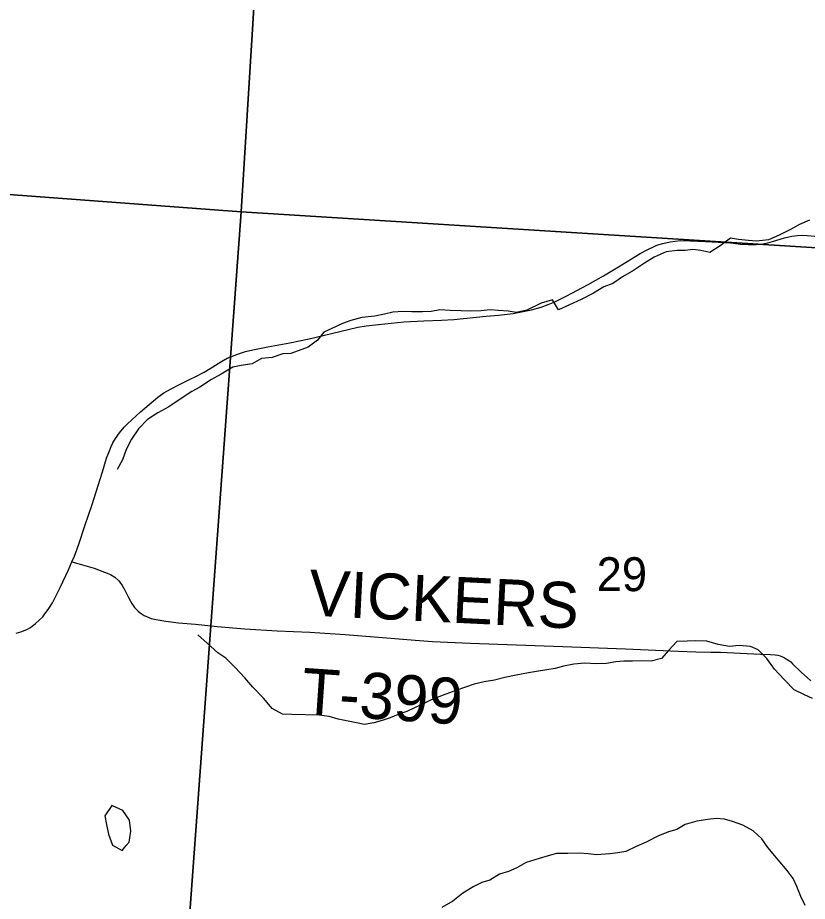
# Model space of a CAD drawing. Extents: x 0 to 34, y 0 to 22.
# Drawn here: x 4.184 to 5.158, y 17.019 to 18.11 of the extents above; entities that cross this region are included whole.
import ezdxf

# ---------------------------------------------------------------- set-up
doc = ezdxf.new("R2010")
doc.units = 0
for name, color, linetype in [('GM_X_Corporation', 7, 'Continuous'), ('GM_X_County_Road', 7, 'Continuous'), ('GM_X_Minor_Lake', 7, 'Continuous'), ('GM_X_Minor_River', 7, 'Continuous'), ('GM_X_Section_Text', 7, 'Continuous'), ('GM_X_Township_Road', 7, 'Continuous'), ('GM_X_Township_Road_Text', 7, 'Continuous')]:
    doc.layers.add(name, color=color, linetype=linetype)

msp = doc.modelspace()

# ---------------------------------------------------------------- linework, layer by layer
at = {"layer": 'GM_X_Corporation'}
for points in [[(3.5166, 18.9866), (4.5247, 18.9179), (4.4596, 17.8697), (3.4457, 17.9455)], [(4.5309, 18.9179), (5.5263, 18.8526), (5.4592, 17.8072), (4.4596, 17.8697), (4.5247, 18.9179)], [(3.4457, 17.9455), (4.4596, 17.8697), (4.3853, 16.8539), (3.3779, 16.9127)], [(4.4596, 17.8697), (5.4592, 17.8072), (5.3901, 16.7843), (4.3853, 16.8539)]]:
    msp.add_lwpolyline(points, close=True, dxfattribs=at)
at = {"layer": 'GM_X_County_Road'}
msp.add_lwpolyline([(4.1821, 17.3498), (4.1877, 17.3514), (4.1934, 17.3536), (4.1961, 17.3549), (4.1988, 17.3563), (4.2013, 17.358), (4.2061, 17.3618), (4.2106, 17.3659), (4.2149, 17.3702), (4.2168, 17.3725), (4.2225, 17.3803), (4.2269, 17.3874), (4.2365, 17.4062), (4.2468, 17.428), (4.2509, 17.4377), (4.254, 17.4449), (4.2595, 17.4596), (4.2669, 17.4824), (4.276, 17.5087), (4.2858, 17.5399), (4.2885, 17.549), (4.2937, 17.5659), (4.2965, 17.5729), (4.2992, 17.5802), (4.3014, 17.5848), (4.3045, 17.5901), (4.3096, 17.5973), (4.3153, 17.604), (4.3195, 17.6084), (4.3355, 17.6229), (4.3569, 17.641), (4.3645, 17.6464), (4.3725, 17.6512), (4.3835, 17.6569), (4.3975, 17.6636), (4.4031, 17.6661), (4.4139, 17.6718), (4.4217, 17.6765), (4.4345, 17.6847), (4.4425, 17.6893), (4.4566, 17.6946), (4.4653, 17.6973), (4.4743, 17.6995), (4.4925, 17.7032), (4.52, 17.7082), (4.5438, 17.7133), (4.5711, 17.7196), (4.6039, 17.7275), (4.6142, 17.7292), (4.6294, 17.731), (4.6605, 17.734), (4.6853, 17.7355), (4.707, 17.736), (4.7221, 17.737), (4.7622, 17.7411), (4.7772, 17.7424), (4.7955, 17.7444), (4.818, 17.7491), (4.83, 17.7523), (4.8386, 17.7554), (4.8469, 17.7588), (4.8607, 17.7656), (4.888, 17.7803), (4.907, 17.7909), (4.9256, 17.802), (4.952, 17.8183), (4.96, 17.8227), (4.9711, 17.8278), (4.974, 17.829), (4.98, 17.8308), (4.9891, 17.8329), (4.9953, 17.8338), (5.0016, 17.8343), (5.014, 17.8342), (5.0327, 17.8334), (5.0636, 17.8315), (5.0699, 17.8308), (5.0761, 17.83), (5.0854, 17.8296), (5.0952, 17.8295), (5.1007, 17.8298), (5.1037, 17.8302), (5.1097, 17.8315), (5.1156, 17.8331), (5.1304, 17.8377), (5.1395, 17.8398), (5.1457, 17.8407), (5.152, 17.841), (5.1583, 17.8407), (5.1676, 17.8397)], dxfattribs=at)
at = {"layer": 'GM_X_Minor_Lake'}
for p, q in [((4.3003, 17.1371), (4.2916, 17.1246)), ((4.3136, 17.1311), (4.3003, 17.1371)), ((4.2916, 17.1246), (4.2936, 17.1136)), ((4.3219, 17.1191), (4.3136, 17.1311)), ((4.2936, 17.1136), (4.2959, 17.1019)), ((4.3235, 17.1054), (4.3219, 17.1191)), ((4.2959, 17.1019), (4.3008, 17.0883)), ((4.3216, 17.0921), (4.3235, 17.1054)), ((4.318, 17.0876), (4.3216, 17.0921)), ((4.3008, 17.0883), (4.313, 17.0815)), ((4.313, 17.0815), (4.318, 17.0876))]:
    msp.add_line(p, q, dxfattribs=at)
at = {"layer": 'GM_X_Minor_River'}
for p, q in [((5.1487, 17.8544), (5.1378, 17.8479)), ((5.1612, 17.8595), (5.1487, 17.8544)), ((5.1378, 17.8479), (5.1235, 17.8409)), ((5.0637, 17.8374), (5.051, 17.8278)), ((5.0736, 17.8359), (5.0637, 17.8374)), ((5.0857, 17.8345), (5.0736, 17.8359)), ((5.0956, 17.8338), (5.0857, 17.8345)), ((5.1103, 17.8355), (5.0956, 17.8338)), ((5.1235, 17.8409), (5.1103, 17.8355)), ((4.9977, 17.822), (4.9844, 17.8207)), ((5.0075, 17.8221), (4.9977, 17.822)), ((5.0173, 17.8233), (5.0075, 17.8221)), ((5.0272, 17.8222), (5.0173, 17.8233)), ((5.0382, 17.8197), (5.0272, 17.8222)), ((5.051, 17.8278), (5.0382, 17.8197)), ((4.9694, 17.8141), (4.9573, 17.8064)), ((4.9844, 17.8207), (4.9694, 17.8141)), ((4.9573, 17.8064), (4.9438, 17.7976)), ((4.9302, 17.7895), (4.9186, 17.7815)), ((4.9438, 17.7976), (4.9302, 17.7895)), ((4.9072, 17.7772), (4.8944, 17.7695)), ((4.9186, 17.7815), (4.9072, 17.7772)), ((4.8944, 17.7695), (4.8794, 17.7618)), ((4.8299, 17.7572), (4.8121, 17.7487)), ((4.8438, 17.7611), (4.8299, 17.7572)), ((4.8515, 17.749), (4.8438, 17.7611)), ((4.8794, 17.7618), (4.8651, 17.7552)), ((4.6468, 17.746), (4.6366, 17.7437)), ((4.6597, 17.7469), (4.6468, 17.746)), ((4.6703, 17.7466), (4.6597, 17.7469)), ((4.6835, 17.7464), (4.6703, 17.7466)), ((4.6941, 17.7468), (4.6835, 17.7464)), ((4.7051, 17.7488), (4.6941, 17.7468)), ((4.7176, 17.7482), (4.7051, 17.7488)), ((4.7312, 17.7475), (4.7176, 17.7482)), ((4.7429, 17.7473), (4.7312, 17.7475)), ((4.7558, 17.7478), (4.7429, 17.7473)), ((4.7671, 17.749), (4.7558, 17.7478)), ((4.7773, 17.748), (4.7671, 17.749)), ((4.7891, 17.7473), (4.7773, 17.748)), ((4.7997, 17.7455), (4.7891, 17.7473)), ((4.8121, 17.7487), (4.7997, 17.7455)), ((4.8651, 17.7552), (4.8515, 17.749)), ((4.5951, 17.7357), (4.5849, 17.7322)), ((4.6087, 17.7396), (4.5951, 17.7357)), ((4.6245, 17.7409), (4.6087, 17.7396)), ((4.6366, 17.7437), (4.6245, 17.7409)), ((4.5717, 17.726), (4.5619, 17.7214)), ((4.5849, 17.7322), (4.5717, 17.726)), ((4.5619, 17.7214), (4.5541, 17.7115)), ((4.5424, 17.703), (4.5212, 17.6952)), ((4.5541, 17.7115), (4.5424, 17.703)), ((4.4982, 17.6902), (4.4849, 17.689)), ((4.511, 17.6948), (4.4982, 17.6902)), ((4.5212, 17.6952), (4.511, 17.6948)), ((4.4596, 17.6802), (4.4494, 17.6783)), ((4.4732, 17.6822), (4.4596, 17.6802)), ((4.4849, 17.689), (4.4732, 17.6822)), ((4.435, 17.6695), (4.423, 17.663)), ((4.4494, 17.6783), (4.435, 17.6695)), ((4.423, 17.663), (4.4086, 17.6534)), ((4.3988, 17.6481), (4.3833, 17.6378)), ((4.4086, 17.6534), (4.3988, 17.6481)), ((4.3833, 17.6378), (4.3705, 17.6294)), ((4.3705, 17.6294), (4.3569, 17.6218)), ((4.3569, 17.6218), (4.344, 17.6134)), ((4.344, 17.6134), (4.3331, 17.6019)), ((4.3331, 17.6019), (4.3244, 17.5894)), ((4.3244, 17.5894), (4.318, 17.5765)), ((4.318, 17.5765), (4.3132, 17.5636)), ((4.3132, 17.5636), (4.3068, 17.5518)), ((4.4177, 17.3374), (4.4063, 17.3476)), ((4.431, 17.3257), (4.4177, 17.3374)), ((4.9973, 17.3396), (4.9876, 17.3289)), ((5.0102, 17.3401), (4.9973, 17.3396)), ((5.02, 17.3402), (5.0102, 17.3401)), ((5.0344, 17.3399), (5.02, 17.3402)), ((5.0484, 17.3359), (5.0344, 17.3399)), ((5.0624, 17.3333), (5.0484, 17.3359)), ((5.0745, 17.3346), (5.0624, 17.3333)), ((5.0882, 17.3336), (5.0745, 17.3346)), ((5.0977, 17.3291), (5.0882, 17.3336)), ((4.4408, 17.3189), (4.431, 17.3257)), ((4.9876, 17.3289), (4.9786, 17.3186)), ((5.1084, 17.3186), (5.0977, 17.3291)), ((4.4522, 17.3076), (4.4408, 17.3189)), ((4.8576, 17.3091), (4.8474, 17.3064)), ((4.8704, 17.3115), (4.8576, 17.3091)), ((4.884, 17.3128), (4.8704, 17.3115)), ((4.8977, 17.3121), (4.884, 17.3128)), ((4.9105, 17.3126), (4.8977, 17.3121)), ((4.9222, 17.3143), (4.9105, 17.3126)), ((4.9321, 17.3151), (4.9222, 17.3143)), ((4.9427, 17.3152), (4.9321, 17.3151)), ((4.9548, 17.3157), (4.9427, 17.3152)), ((4.9657, 17.3154), (4.9548, 17.3157)), ((4.9786, 17.3186), (4.9657, 17.3154)), ((5.1179, 17.3054), (5.1084, 17.3186)), ((4.4644, 17.2948), (4.4522, 17.3076)), ((4.799, 17.298), (4.7851, 17.2952)), ((4.8142, 17.3008), (4.799, 17.298)), ((4.824, 17.3024), (4.8142, 17.3008)), ((4.8368, 17.3048), (4.824, 17.3024)), ((4.8474, 17.3064), (4.8368, 17.3048)), ((5.1298, 17.2927), (5.1179, 17.3054)), ((4.4743, 17.2831), (4.4644, 17.2948)), ((4.7473, 17.2869), (4.7367, 17.2834)), ((4.7598, 17.2897), (4.7473, 17.2869)), ((4.7722, 17.2917), (4.7598, 17.2897)), ((4.7851, 17.2952), (4.7722, 17.2917)), ((5.142, 17.2799), (5.1298, 17.2927)), ((4.4875, 17.2695), (4.4743, 17.2831)), ((4.7247, 17.2791), (4.7092, 17.2733)), ((4.7367, 17.2834), (4.7247, 17.2791)), ((5.1549, 17.2739), (5.142, 17.2799)), ((4.4978, 17.257), (4.4875, 17.2695)), ((4.6941, 17.2675), (4.6843, 17.2628)), ((4.7092, 17.2733), (4.6941, 17.2675)), ((5.1648, 17.2691), (5.1549, 17.2739)), ((4.5107, 17.2499), (4.4978, 17.257)), ((4.6738, 17.2578), (4.664, 17.2532)), ((4.6843, 17.2628), (4.6738, 17.2578)), ((4.5219, 17.2495), (4.5107, 17.2499)), ((4.5562, 17.2488), (4.5219, 17.2495)), ((4.5683, 17.247), (4.5562, 17.2488)), ((4.5793, 17.2437), (4.5683, 17.247)), ((4.602, 17.2393), (4.5793, 17.2437)), ((4.6436, 17.2454), (4.6338, 17.2419)), ((4.6534, 17.2493), (4.6436, 17.2454)), ((4.664, 17.2532), (4.6534, 17.2493)), ((4.6119, 17.2372), (4.602, 17.2393)), ((4.6236, 17.2392), (4.6119, 17.2372)), ((4.6338, 17.2419), (4.6236, 17.2392)), ((5.0076, 17.1138), (4.9974, 17.1077)), ((5.0219, 17.1177), (5.0076, 17.1138)), ((5.0356, 17.1198), (5.0219, 17.1177)), ((5.0461, 17.121), (5.0356, 17.1198)), ((5.0564, 17.1203), (5.0461, 17.121)), ((5.0662, 17.1174), (5.0564, 17.1203)), ((5.0787, 17.1129), (5.0662, 17.1174)), ((5.0917, 17.1059), (5.0787, 17.1129)), ((4.9869, 17.1045), (4.9741, 17.0995)), ((4.9974, 17.1077), (4.9869, 17.1045)), ((5.1023, 17.0961), (5.0917, 17.1059)), ((4.9597, 17.0918), (4.9462, 17.086)), ((4.9741, 17.0995), (4.9597, 17.0918)), ((5.1096, 17.0852), (5.1023, 17.0961)), ((4.9345, 17.0802), (4.9247, 17.0786)), ((4.9462, 17.086), (4.9345, 17.0802)), ((5.1226, 17.0701), (5.1096, 17.0852)), ((4.8275, 17.0716), (4.8116, 17.0666)), ((4.8388, 17.0751), (4.8275, 17.0716)), ((4.849, 17.0779), (4.8388, 17.0751)), ((4.863, 17.078), (4.849, 17.0779)), ((4.877, 17.0785), (4.863, 17.078)), ((4.888, 17.0775), (4.877, 17.0785)), ((4.8982, 17.0764), (4.888, 17.0775)), ((4.9145, 17.0777), (4.8982, 17.0764)), ((4.9247, 17.0786), (4.9145, 17.0777)), ((5.1337, 17.057), (5.1226, 17.0701)), ((4.8, 17.0604), (4.7898, 17.0558)), ((4.8116, 17.0666), (4.8, 17.0604)), ((4.7785, 17.0522), (4.7668, 17.0449)), ((4.7898, 17.0558), (4.7785, 17.0522)), ((5.141, 17.0472), (5.1337, 17.057)), ((5.1456, 17.037), (5.141, 17.0472)), ((4.7468, 17.0372), (4.7333, 17.0291)), ((4.7566, 17.0422), (4.7468, 17.0372)), ((4.7668, 17.0449), (4.7566, 17.0422)), ((5.1506, 17.0249), (5.1456, 17.037)), ((4.7333, 17.0291), (4.7209, 17.0191)), ((5.1557, 17.0136), (5.1506, 17.0249)), ((4.7209, 17.0191), (4.7073, 17.0114))]:
    msp.add_line(p, q, dxfattribs=at)
at = {"layer": 'GM_X_Township_Road'}
msp.add_lwpolyline([(4.2509, 17.4377), (4.2581, 17.4357), (4.2667, 17.4334), (4.2782, 17.4299), (4.2963, 17.4232), (4.2984, 17.4222), (4.3039, 17.4188), (4.3088, 17.4143), (4.3099, 17.413), (4.3131, 17.4085), (4.3163, 17.4031), (4.3202, 17.3947), (4.323, 17.3892), (4.3247, 17.3865), (4.3283, 17.3815), (4.3304, 17.3792), (4.3326, 17.3771), (4.335, 17.3751), (4.3375, 17.3733), (4.3402, 17.3717), (4.3429, 17.3704), (4.3458, 17.3691), (4.3487, 17.3681), (4.3547, 17.3666), (4.3669, 17.3645), (4.3823, 17.3626), (4.4036, 17.3608), (4.43, 17.358), (4.4641, 17.3551), (4.504, 17.3529), (4.5446, 17.351), (4.588, 17.3483), (4.6343, 17.3447), (4.6744, 17.3411), (4.696, 17.3394), (4.7423, 17.3375), (4.8566, 17.3336), (4.934, 17.3306), (4.9991, 17.3276), (5.0207, 17.3267), (5.0392, 17.3266), (5.0514, 17.3264), (5.1006, 17.3239), (5.1128, 17.3236), (5.1189, 17.3233), (5.122, 17.3229), (5.125, 17.322), (5.1277, 17.3208), (5.1302, 17.3195), (5.1354, 17.3162), (5.1379, 17.3143), (5.1402, 17.3122), (5.1512, 17.3013), (5.1581, 17.295), (5.1629, 17.2912)], dxfattribs=at)

# ---------------------------------------------------------------- texts
at = {"layer": 'GM_X_Section_Text'}
msp.add_text('29', height=0.04186, rotation=0, dxfattribs=at).set_placement((4.8984, 17.4017))
at = {"layer": 'GM_X_Township_Road_Text'}
for s, rotation, p in [('VICKERS', 357.1667, (4.5421, 17.3717)), ('T-399', 356.0742, (4.5329, 17.2504))]:
    msp.add_text(s, height=0.05682, rotation=rotation, dxfattribs=at).set_placement(p)

doc.saveas('drawing.dxf')
